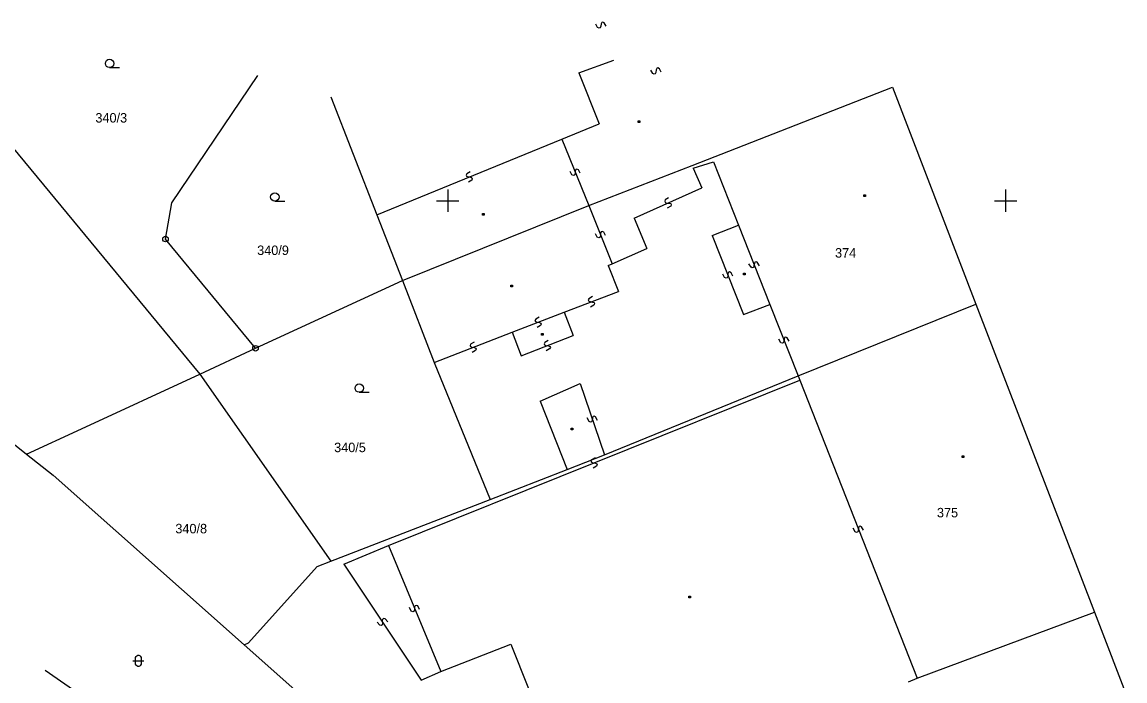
# Model space of a CAD drawing. Extents: x -492379 to -491966, y -1126153 to -1125860.
# Drawn here: x -492292.9 to -492233.6, y -1125895.8 to -1125860.4 of the extents above; entities that cross this region are included whole.
import ezdxf

# ---------------------------------------------------------------- set-up
doc = ezdxf.new("R2010")
doc.units = 0
doc.layers.add('katastrální mapa', color=7, linetype='Continuous')
doc.layers.add('síť', color=7, linetype='Continuous')

msp = doc.modelspace()

# ---------------------------------------------------------------- linework, layer by layer
at = {"layer": 'katastrální mapa'}
for p, q in [((-492261.94, -1125860.67), (-492262.04, -1125860.49)), ((-492261.75, -1125860.48), (-492261.77, -1125860.61)), ((-492261.72, -1125860.4), (-492261.75, -1125860.48)), ((-492261.66, -1125860.38), (-492261.72, -1125860.4)), ((-492261.58, -1125860.42), (-492261.66, -1125860.38)), ((-492261.48, -1125860.6), (-492261.58, -1125860.42)), ((-492261.86, -1125860.71), (-492261.94, -1125860.67)), ((-492261.8, -1125860.69), (-492261.86, -1125860.71)), ((-492261.77, -1125860.61), (-492261.8, -1125860.69)), ((-492288.19, -1125862.83), (-492287.66, -1125862.83)), ((-492262.95, -1125863.11), (-492261.06, -1125862.43)), ((-492258.79, -1125862.95), (-492258.8, -1125863.09)), ((-492258.75, -1125862.88), (-492258.79, -1125862.95)), ((-492258.7, -1125862.85), (-492258.75, -1125862.88)), ((-492258.62, -1125862.89), (-492258.7, -1125862.85)), ((-492258.52, -1125863.07), (-492258.62, -1125862.89)), ((-492284.84, -1125870.11), (-492280.22, -1125863.25)), ((-492262.95, -1125863.11), (-492261.85, -1125865.85)), ((-492258.97, -1125863.15), (-492259.07, -1125862.97)), ((-492258.89, -1125863.19), (-492258.97, -1125863.15)), ((-492258.84, -1125863.16), (-492258.89, -1125863.19)), ((-492258.8, -1125863.09), (-492258.84, -1125863.16)), ((-492256.86, -1125868.1), (-492246.08, -1125863.89)), ((-492246.08, -1125863.89), (-492241.59, -1125875.56)), ((-492276.28, -1125864.4), (-492275.08, -1125867.5)), ((-492263.87, -1125866.68), (-492261.85, -1125865.85)), ((-492259.76, -1125865.69), (-492259.67, -1125865.69)), ((-492259.76, -1125865.78), (-492259.76, -1125865.69)), ((-492259.67, -1125865.78), (-492259.76, -1125865.78)), ((-492259.67, -1125865.69), (-492259.67, -1125865.78)), ((-492294.03, -1125866.37), (-492283.34, -1125879.33)), ((-492273.82, -1125870.76), (-492263.87, -1125866.68)), ((-492263.87, -1125866.68), (-492262.42, -1125870.26)), ((-492275.08, -1125867.5), (-492273.82, -1125870.76)), ((-492263.05, -1125868.3), (-492263.11, -1125868.32)), ((-492262.97, -1125868.34), (-492263.05, -1125868.3)), ((-492262.42, -1125870.26), (-492256.86, -1125868.1)), ((-492256.8, -1125868.24), (-492255.7, -1125867.9)), ((-492256.8, -1125868.24), (-492256.33, -1125869.31)), ((-492255.7, -1125867.9), (-492254.36, -1125871.31)), ((-492268.98, -1125868.55), (-492269.01, -1125868.63)), ((-492269.01, -1125868.63), (-492268.99, -1125868.68)), ((-492268.99, -1125868.68), (-492268.91, -1125868.72)), ((-492268.8, -1125868.44), (-492268.98, -1125868.55)), ((-492268.91, -1125868.72), (-492268.78, -1125868.72)), ((-492268.71, -1125868.89), (-492268.89, -1125869)), ((-492268.78, -1125868.72), (-492268.7, -1125868.76)), ((-492268.68, -1125868.81), (-492268.71, -1125868.89)), ((-492268.7, -1125868.76), (-492268.68, -1125868.81)), ((-492263.32, -1125868.6), (-492263.42, -1125868.42)), ((-492263.24, -1125868.64), (-492263.32, -1125868.6)), ((-492263.18, -1125868.62), (-492263.24, -1125868.64)), ((-492263.15, -1125868.54), (-492263.18, -1125868.62)), ((-492263.14, -1125868.4), (-492263.15, -1125868.54)), ((-492263.11, -1125868.32), (-492263.14, -1125868.4)), ((-492262.87, -1125868.52), (-492262.97, -1125868.34)), ((-492259.98, -1125870.93), (-492256.33, -1125869.31)), ((-492279.3, -1125870.02), (-492278.77, -1125870.02)), ((-492258.3, -1125869.95), (-492258.33, -1125870.03)), ((-492258.33, -1125870.03), (-492258.3, -1125870.09)), ((-492258.12, -1125869.84), (-492258.3, -1125869.95)), ((-492247.63, -1125869.68), (-492247.54, -1125869.68)), ((-492247.63, -1125869.77), (-492247.63, -1125869.68)), ((-492247.54, -1125869.77), (-492247.63, -1125869.77)), ((-492247.54, -1125869.68), (-492247.54, -1125869.77)), ((-492285.18, -1125872.06), (-492284.84, -1125870.11)), ((-492272.44, -1125874.3), (-492262.42, -1125870.26)), ((-492262.42, -1125870.26), (-492261.15, -1125873.39)), ((-492258.3, -1125870.09), (-492258.22, -1125870.12)), ((-492258.22, -1125870.12), (-492258.09, -1125870.12)), ((-492258.01, -1125870.29), (-492258.19, -1125870.4)), ((-492258.09, -1125870.12), (-492258.01, -1125870.15)), ((-492258.01, -1125870.15), (-492257.98, -1125870.21)), ((-492257.98, -1125870.21), (-492258.01, -1125870.29)), ((-492308.33, -1125871.26), (-492292.65, -1125883.63)), ((-492273.82, -1125870.76), (-492272.44, -1125874.3)), ((-492268.13, -1125870.69), (-492268.04, -1125870.69)), ((-492268.13, -1125870.78), (-492268.13, -1125870.69)), ((-492268.04, -1125870.78), (-492268.13, -1125870.78)), ((-492268.04, -1125870.69), (-492268.04, -1125870.78)), ((-492259.98, -1125870.93), (-492259.3, -1125872.57)), ((-492261.96, -1125871.96), (-492262.06, -1125871.78)), ((-492261.78, -1125871.76), (-492261.79, -1125871.89)), ((-492261.75, -1125871.68), (-492261.78, -1125871.76)), ((-492261.69, -1125871.66), (-492261.75, -1125871.68)), ((-492261.61, -1125871.69), (-492261.69, -1125871.66)), ((-492261.51, -1125871.87), (-492261.61, -1125871.69)), ((-492255.78, -1125871.87), (-492254.36, -1125871.31)), ((-492254.36, -1125871.31), (-492252.68, -1125875.58)), ((-492280.34, -1125877.94), (-492285.18, -1125872.06)), ((-492261.88, -1125871.99), (-492261.96, -1125871.96)), ((-492261.82, -1125871.97), (-492261.88, -1125871.99)), ((-492261.79, -1125871.89), (-492261.82, -1125871.97)), ((-492255.78, -1125871.87), (-492254.09, -1125876.13)), ((-492261.15, -1125873.39), (-492259.3, -1125872.57)), ((-492261.38, -1125873.49), (-492261.15, -1125873.39)), ((-492261.38, -1125873.49), (-492260.81, -1125874.88)), ((-492253.69, -1125873.58), (-492253.8, -1125873.39)), ((-492253.62, -1125873.61), (-492253.69, -1125873.58)), ((-492253.56, -1125873.59), (-492253.62, -1125873.61)), ((-492253.53, -1125873.51), (-492253.56, -1125873.59)), ((-492253.51, -1125873.38), (-492253.53, -1125873.51)), ((-492253.48, -1125873.3), (-492253.51, -1125873.38)), ((-492253.42, -1125873.28), (-492253.48, -1125873.3)), ((-492253.35, -1125873.31), (-492253.42, -1125873.28)), ((-492253.24, -1125873.5), (-492253.35, -1125873.31)), ((-492255.11, -1125874.13), (-492255.21, -1125873.95)), ((-492255.03, -1125874.17), (-492255.11, -1125874.13)), ((-492254.97, -1125874.14), (-492255.03, -1125874.17)), ((-492254.94, -1125874.07), (-492254.97, -1125874.14)), ((-492254.93, -1125873.93), (-492254.94, -1125874.07)), ((-492254.9, -1125873.86), (-492254.93, -1125873.93)), ((-492254.84, -1125873.83), (-492254.9, -1125873.86)), ((-492254.76, -1125873.87), (-492254.84, -1125873.83)), ((-492254.66, -1125874.05), (-492254.76, -1125873.87)), ((-492254.09, -1125873.89), (-492254, -1125873.89)), ((-492254.09, -1125873.98), (-492254.09, -1125873.89)), ((-492254, -1125873.98), (-492254.09, -1125873.98)), ((-492254, -1125873.89), (-492254, -1125873.98)), ((-492280.34, -1125877.94), (-492272.44, -1125874.3)), ((-492272.44, -1125874.3), (-492270.73, -1125878.7)), ((-492266.61, -1125874.55), (-492266.52, -1125874.55)), ((-492266.61, -1125874.64), (-492266.61, -1125874.55)), ((-492266.52, -1125874.64), (-492266.61, -1125874.64)), ((-492266.52, -1125874.55), (-492266.52, -1125874.64)), ((-492263.74, -1125876), (-492260.81, -1125874.88)), ((-492262.41, -1125875.27), (-492262.44, -1125875.34)), ((-492262.44, -1125875.34), (-492262.42, -1125875.4)), ((-492262.42, -1125875.4), (-492262.34, -1125875.43)), ((-492262.22, -1125875.16), (-492262.41, -1125875.27)), ((-492266.54, -1125877.08), (-492263.74, -1125876)), ((-492263.74, -1125876), (-492263.25, -1125877.26)), ((-492262.34, -1125875.43), (-492262.21, -1125875.45)), ((-492262.14, -1125875.61), (-492262.33, -1125875.72)), ((-492262.21, -1125875.45), (-492262.13, -1125875.48)), ((-492262.11, -1125875.54), (-492262.14, -1125875.61)), ((-492262.13, -1125875.48), (-492262.11, -1125875.54)), ((-492254.09, -1125876.13), (-492252.68, -1125875.58)), ((-492252.68, -1125875.58), (-492251.16, -1125879.43)), ((-492251.16, -1125879.43), (-492241.59, -1125875.56)), ((-492241.59, -1125875.56), (-492235.22, -1125892.14)), ((-492265.27, -1125876.37), (-492265.31, -1125876.44)), ((-492265.31, -1125876.44), (-492265.28, -1125876.5)), ((-492265.28, -1125876.5), (-492265.21, -1125876.53)), ((-492265.09, -1125876.26), (-492265.27, -1125876.37)), ((-492265.21, -1125876.53), (-492265.07, -1125876.55)), ((-492265.07, -1125876.55), (-492265, -1125876.58)), ((-492265, -1125876.58), (-492264.97, -1125876.64)), ((-492270.73, -1125878.7), (-492266.54, -1125877.08)), ((-492266.54, -1125877.08), (-492266.05, -1125878.34)), ((-492265.01, -1125876.71), (-492265.19, -1125876.82)), ((-492264.97, -1125876.64), (-492265.01, -1125876.71)), ((-492264.96, -1125877.14), (-492264.87, -1125877.14)), ((-492264.96, -1125877.23), (-492264.96, -1125877.14)), ((-492264.87, -1125877.14), (-492264.87, -1125877.23)), ((-492268.77, -1125877.72), (-492268.8, -1125877.79)), ((-492268.8, -1125877.79), (-492268.78, -1125877.85)), ((-492268.58, -1125877.61), (-492268.77, -1125877.72)), ((-492266.05, -1125878.34), (-492263.25, -1125877.26)), ((-492264.87, -1125877.23), (-492264.96, -1125877.23)), ((-492264.78, -1125877.63), (-492264.82, -1125877.7)), ((-492264.82, -1125877.7), (-492264.79, -1125877.76)), ((-492264.79, -1125877.76), (-492264.72, -1125877.79)), ((-492264.6, -1125877.52), (-492264.78, -1125877.63)), ((-492264.72, -1125877.79), (-492264.58, -1125877.81)), ((-492252.09, -1125877.64), (-492252.2, -1125877.45)), ((-492252.02, -1125877.67), (-492252.09, -1125877.64)), ((-492251.96, -1125877.65), (-492252.02, -1125877.67)), ((-492251.93, -1125877.57), (-492251.96, -1125877.65)), ((-492251.91, -1125877.44), (-492251.93, -1125877.57)), ((-492251.88, -1125877.36), (-492251.91, -1125877.44)), ((-492251.82, -1125877.34), (-492251.88, -1125877.36)), ((-492251.75, -1125877.37), (-492251.82, -1125877.34)), ((-492251.64, -1125877.56), (-492251.75, -1125877.37)), ((-492283.34, -1125879.33), (-492280.34, -1125877.94)), ((-492268.78, -1125877.85), (-492268.7, -1125877.88)), ((-492268.7, -1125877.88), (-492268.57, -1125877.9)), ((-492268.5, -1125878.06), (-492268.69, -1125878.17)), ((-492268.57, -1125877.9), (-492268.49, -1125877.93)), ((-492268.47, -1125877.99), (-492268.5, -1125878.06)), ((-492268.49, -1125877.93), (-492268.47, -1125877.99)), ((-492264.52, -1125877.97), (-492264.7, -1125878.08)), ((-492264.58, -1125877.81), (-492264.51, -1125877.84)), ((-492264.48, -1125877.9), (-492264.52, -1125877.97)), ((-492264.51, -1125877.84), (-492264.48, -1125877.9)), ((-492270.73, -1125878.7), (-492267.71, -1125886.07)), ((-492289.69, -1125882.27), (-492283.34, -1125879.33)), ((-492283.34, -1125879.33), (-492276.29, -1125889.39)), ((-492261.57, -1125883.67), (-492251.16, -1125879.43)), ((-492251.16, -1125879.43), (-492251.07, -1125879.66)), ((-492273.19, -1125888.56), (-492251.07, -1125879.66)), ((-492265.03, -1125880.78), (-492262.88, -1125879.84)), ((-492262.88, -1125879.84), (-492261.57, -1125883.67)), ((-492251.07, -1125879.66), (-492244.76, -1125895.7)), ((-492274.76, -1125880.31), (-492274.23, -1125880.31)), ((-492265.03, -1125880.78), (-492263.57, -1125884.46)), ((-492262.4, -1125881.88), (-492262.5, -1125881.69)), ((-492262.33, -1125881.92), (-492262.4, -1125881.88)), ((-492262.27, -1125881.9), (-492262.33, -1125881.92)), ((-492262.23, -1125881.82), (-492262.27, -1125881.9)), ((-492262.22, -1125881.69), (-492262.23, -1125881.82)), ((-492262.18, -1125881.61), (-492262.22, -1125881.69)), ((-492262.12, -1125881.59), (-492262.18, -1125881.61)), ((-492262.05, -1125881.63), (-492262.12, -1125881.59)), ((-492261.95, -1125881.82), (-492262.05, -1125881.63)), ((-492292.65, -1125883.63), (-492289.69, -1125882.27)), ((-492263.37, -1125882.24), (-492263.28, -1125882.24)), ((-492263.37, -1125882.33), (-492263.37, -1125882.24)), ((-492263.28, -1125882.33), (-492263.37, -1125882.33)), ((-492263.28, -1125882.24), (-492263.28, -1125882.33)), ((-492292.65, -1125883.63), (-492291.22, -1125884.76)), ((-492263.57, -1125884.46), (-492261.57, -1125883.67)), ((-492262.26, -1125883.94), (-492262.3, -1125884.02)), ((-492262.3, -1125884.02), (-492262.27, -1125884.07)), ((-492262.27, -1125884.07), (-492262.2, -1125884.1)), ((-492262.08, -1125883.83), (-492262.26, -1125883.94)), ((-492262.2, -1125884.1), (-492262.06, -1125884.12)), ((-492262, -1125884.28), (-492262.18, -1125884.39)), ((-492262.06, -1125884.12), (-492261.99, -1125884.15)), ((-492261.96, -1125884.2), (-492262, -1125884.28)), ((-492261.99, -1125884.15), (-492261.96, -1125884.2)), ((-492242.33, -1125883.73), (-492242.24, -1125883.73)), ((-492242.33, -1125883.82), (-492242.33, -1125883.73)), ((-492242.24, -1125883.82), (-492242.33, -1125883.82)), ((-492242.24, -1125883.73), (-492242.24, -1125883.82)), ((-492291.22, -1125884.76), (-492280.94, -1125893.9)), ((-492267.71, -1125886.07), (-492263.57, -1125884.46)), ((-492276.29, -1125889.39), (-492267.71, -1125886.07)), ((-492248.09, -1125887.81), (-492248.19, -1125887.63)), ((-492248.01, -1125887.85), (-492248.09, -1125887.81)), ((-492247.95, -1125887.82), (-492248.01, -1125887.85)), ((-492247.92, -1125887.75), (-492247.95, -1125887.82)), ((-492247.91, -1125887.61), (-492247.92, -1125887.75)), ((-492247.88, -1125887.54), (-492247.91, -1125887.61)), ((-492247.82, -1125887.51), (-492247.88, -1125887.54)), ((-492247.74, -1125887.55), (-492247.82, -1125887.51)), ((-492247.64, -1125887.73), (-492247.74, -1125887.55)), ((-492275.59, -1125889.55), (-492273.19, -1125888.56)), ((-492273.19, -1125888.56), (-492270.38, -1125895.34)), ((-492277.03, -1125889.68), (-492276.29, -1125889.39)), ((-492275.59, -1125889.55), (-492271.43, -1125895.8)), ((-492280.71, -1125893.79), (-492277.03, -1125889.68)), ((-492257.04, -1125891.28), (-492256.95, -1125891.28)), ((-492257.04, -1125891.37), (-492257.04, -1125891.28)), ((-492256.95, -1125891.37), (-492257.04, -1125891.37)), ((-492256.95, -1125891.28), (-492256.95, -1125891.37)), ((-492271.96, -1125892.09), (-492272.06, -1125891.9)), ((-492271.79, -1125892.02), (-492271.82, -1125892.1)), ((-492271.78, -1125891.88), (-492271.79, -1125892.02)), ((-492271.75, -1125891.8), (-492271.78, -1125891.88)), ((-492271.69, -1125891.78), (-492271.75, -1125891.8)), ((-492271.61, -1125891.81), (-492271.69, -1125891.78)), ((-492271.51, -1125892), (-492271.61, -1125891.81)), ((-492273.5, -1125892.53), (-492273.52, -1125892.61)), ((-492273.52, -1125892.61), (-492273.5, -1125892.74)), ((-492273.45, -1125892.49), (-492273.5, -1125892.53)), ((-492273.37, -1125892.51), (-492273.45, -1125892.49)), ((-492273.23, -1125892.67), (-492273.37, -1125892.51)), ((-492271.88, -1125892.12), (-492271.96, -1125892.09)), ((-492271.82, -1125892.1), (-492271.88, -1125892.12)), ((-492244.76, -1125895.7), (-492235.22, -1125892.14)), ((-492235.22, -1125892.14), (-492230.86, -1125903.49)), ((-492273.65, -1125892.84), (-492273.79, -1125892.68)), ((-492273.57, -1125892.86), (-492273.65, -1125892.84)), ((-492273.52, -1125892.82), (-492273.57, -1125892.86)), ((-492273.5, -1125892.74), (-492273.52, -1125892.82)), ((-492280.94, -1125893.9), (-492280.71, -1125893.79)), ((-492280.94, -1125893.9), (-492268.29, -1125905.14)), ((-492270.38, -1125895.34), (-492266.61, -1125893.86)), ((-492266.61, -1125893.86), (-492265.66, -1125896.25)), ((-492286.94, -1125894.76), (-492286.34, -1125894.76)), ((-492286.79, -1125894.58), (-492286.76, -1125894.52)), ((-492286.79, -1125894.94), (-492286.79, -1125894.58)), ((-492286.76, -1125895), (-492286.79, -1125894.94)), ((-492286.76, -1125894.52), (-492286.73, -1125894.49)), ((-492286.73, -1125894.49), (-492286.67, -1125894.46)), ((-492286.67, -1125894.46), (-492286.61, -1125894.46)), ((-492286.61, -1125894.46), (-492286.55, -1125894.49)), ((-492286.55, -1125894.49), (-492286.52, -1125894.52)), ((-492286.52, -1125894.52), (-492286.49, -1125894.58)), ((-492286.49, -1125894.94), (-492286.52, -1125895)), ((-492286.49, -1125894.58), (-492286.49, -1125894.94)), ((-492291.65, -1125895.27), (-492258.01, -1125918.53)), ((-492286.73, -1125895.03), (-492286.76, -1125895)), ((-492286.67, -1125895.06), (-492286.73, -1125895.03)), ((-492286.61, -1125895.06), (-492286.67, -1125895.06)), ((-492286.55, -1125895.03), (-492286.61, -1125895.06)), ((-492286.52, -1125895), (-492286.55, -1125895.03)), ((-492271.43, -1125895.8), (-492270.38, -1125895.34)), ((-492245.22, -1125895.89), (-492244.76, -1125895.7))]:
    msp.add_line(p, q, dxfattribs=at)
for centre, radius in [((-492288.19, -1125862.605), 0.225), ((-492279.3, -1125869.795), 0.225), ((-492285.18, -1125872.06), 0.15), ((-492285.18, -1125872.06), 0.003), ((-492280.34, -1125877.94), 0.15), ((-492280.34, -1125877.94), 0.003), ((-492274.76, -1125880.085), 0.225)]:
    msp.add_circle(centre, radius, dxfattribs=at)
at = {"layer": 'síť'}
for p, q in [((-492270, -1125869.4), (-492270, -1125870.6)), ((-492240, -1125869.4), (-492240, -1125870.6)), ((-492270.6, -1125870), (-492269.4, -1125870)), ((-492240.6, -1125870), (-492239.4, -1125870))]:
    msp.add_line(p, q, dxfattribs=at)

# ---------------------------------------------------------------- texts
at = {"layer": 'katastrální mapa'}
for s, p in [('340/3', (-492288.95, -1125865.79)), ('340/9', (-492280.25, -1125872.92)), ('374', (-492249.17, -1125873.06)), ('340/5', (-492276.11, -1125883.53)), ('375', (-492243.69, -1125887.04)), ('340/8', (-492284.65, -1125887.9))]:
    msp.add_text(s, height=0.51, dxfattribs=at).set_placement(p)

doc.saveas('drawing.dxf')
